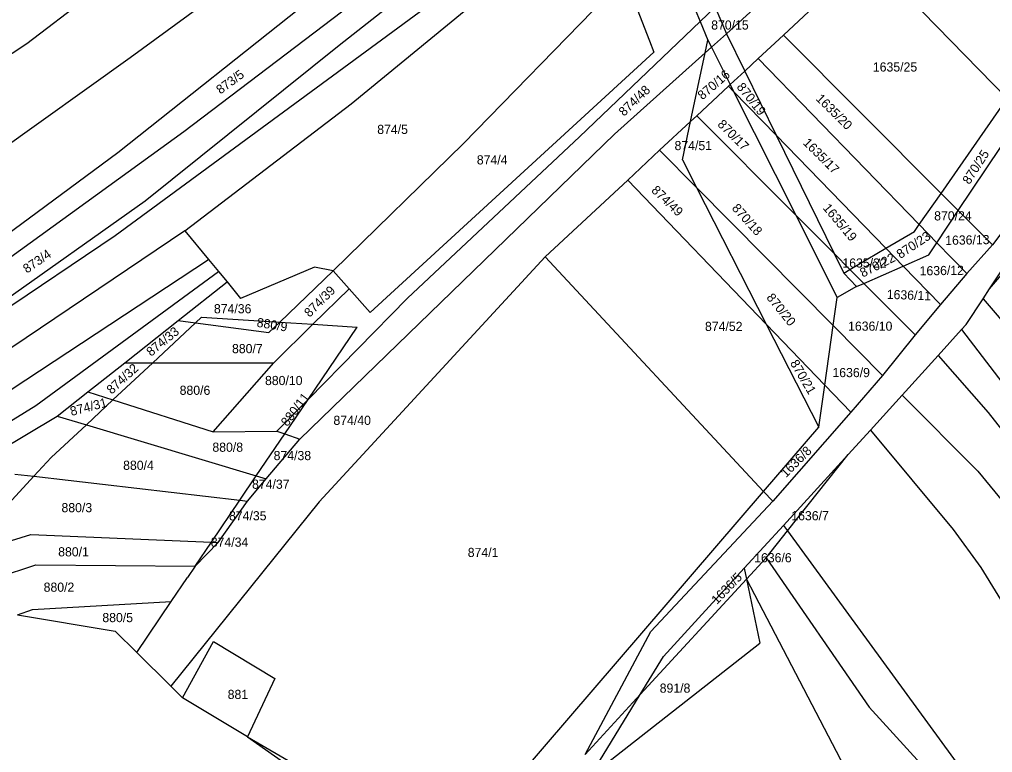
# Model space of a CAD drawing. Extents: x -563148 to -561712, y -1182311 to -1179502.
# Drawn here: x -562408.6 to -562249.3, y -1179894.3 to -1179774.2 of the extents above; entities that cross this region are included whole.
import ezdxf

# ---------------------------------------------------------------- set-up
doc = ezdxf.new("R2010")
doc.units = 0
for name, color, linetype in [('Vrstva 55', 7, 'Continuous'), ('Vrstva 56', 7, 'Continuous'), ('Vrstva 57', 7, 'Continuous')]:
    doc.layers.add(name, color=color, linetype=linetype)

msp = doc.modelspace()

# ---------------------------------------------------------------- linework, layer by layer
at = {"layer": 'Vrstva 55'}
for p, q in [((-562407.37, -1179778.19), (-562321.26, -1179711.9)), ((-562292.88, -1179776.56), (-562248.55, -1179735.96)), ((-562350.32, -1179751.09), (-562390.44, -1179780.54)), ((-562332.98, -1179755.64), (-562381.7, -1179792.64)), ((-562354.31, -1179788.07), (-562314.2, -1179755.13)), ((-562356.25, -1179778.44), (-562332.91, -1179760.03)), ((-562283.55, -1179776.79), (-562269.66, -1179763.85)), ((-562269.66, -1179763.85), (-562246.9, -1179787.18)), ((-562300.75, -1179765.98), (-562297.18, -1179774.57)), ((-562335.89, -1179794.56), (-562309.48, -1179767.37)), ((-562392.89, -1179809.58), (-562341.3, -1179771.67)), ((-562361.02, -1179771.07), (-562392.48, -1179796.07)), ((-562307.48, -1179772.55), (-562305.48, -1179777.73)), ((-562297.18, -1179774.57), (-562294.72, -1179772.22)), ((-562294.72, -1179772.22), (-562292.88, -1179776.56)), ((-562316.94, -1179793.43), (-562297.18, -1179774.57)), ((-562297.18, -1179774.57), (-562295.91, -1179777.64)), ((-562305.48, -1179777.73), (-562304.76, -1179779.6)), ((-562296.34, -1179779.67), (-562295.91, -1179777.64)), ((-562295.34, -1179778.77), (-562292.88, -1179776.56)), ((-562292.88, -1179776.56), (-562289.88, -1179782.69)), ((-562287.68, -1179780.64), (-562283.55, -1179776.79)), ((-562283.55, -1179776.79), (-562257.74, -1179802.71)), ((-562459.54, -1179811.99), (-562407.37, -1179778.19)), ((-562388.02, -1179803.91), (-562356.25, -1179778.44)), ((-562304.76, -1179779.6), (-562351.16, -1179822.19)), ((-562311.21, -1179793.04), (-562296.34, -1179779.67)), ((-562298.73, -1179790.93), (-562296.34, -1179779.67)), ((-562296.34, -1179779.67), (-562295.34, -1179778.77)), ((-562390.44, -1179780.54), (-562423.79, -1179804.26)), ((-562289.88, -1179782.69), (-562287.68, -1179780.64)), ((-562287.68, -1179780.64), (-562261.3, -1179807.82)), ((-562292.26, -1179784.9), (-562289.88, -1179782.69)), ((-562289.88, -1179782.69), (-562284.74, -1179793.17)), ((-562297.72, -1179789.99), (-562292.53, -1179785.16)), ((-562292.53, -1179785.16), (-562292.26, -1179784.9)), ((-562292.53, -1179785.16), (-562291.7, -1179786.02)), ((-562291.7, -1179786.02), (-562284.74, -1179793.17)), ((-562257.74, -1179802.71), (-562246.9, -1179787.18)), ((-562381.5, -1179808.86), (-562354.31, -1179788.07)), ((-562249.79, -1179818.34), (-562230.69, -1179789.21)), ((-562298.73, -1179790.93), (-562297.72, -1179789.99)), ((-562297.72, -1179789.99), (-562281.5, -1179806.28)), ((-562254.92, -1179805.54), (-562244.38, -1179789.76)), ((-562303.8, -1179795.65), (-562298.73, -1179790.93)), ((-562300.07, -1179797.22), (-562298.73, -1179790.93)), ((-562381.7, -1179792.64), (-562424.16, -1179823.4)), ((-562362.67, -1179842.95), (-562311.21, -1179793.04)), ((-562345.08, -1179819.89), (-562316.94, -1179793.43)), ((-562284.74, -1179793.17), (-562275.26, -1179812.55)), ((-562284.74, -1179793.17), (-562266.76, -1179811.7)), ((-562357.22, -1179815.38), (-562335.89, -1179794.56)), ((-562392.48, -1179796.07), (-562420.23, -1179816.57)), ((-562309.03, -1179800.53), (-562303.8, -1179795.65)), ((-562303.8, -1179795.65), (-562297.76, -1179801.76)), ((-562238.13, -1179796.16), (-562249.33, -1179811.15)), ((-562300.07, -1179797.22), (-562297.76, -1179801.76)), ((-562322.54, -1179813.11), (-562309.03, -1179800.53)), ((-562309.03, -1179800.53), (-562286.36, -1179824.12)), ((-562297.76, -1179801.76), (-562275.39, -1179824.36)), ((-562297.76, -1179801.76), (-562286.36, -1179824.12)), ((-562261.3, -1179807.82), (-562257.74, -1179802.71)), ((-562257.74, -1179802.71), (-562254.92, -1179805.54)), ((-562417.57, -1179824.87), (-562388.02, -1179803.91)), ((-562281.5, -1179806.28), (-562275.26, -1179812.55)), ((-562258.42, -1179810.79), (-562254.92, -1179805.54)), ((-562254.92, -1179805.54), (-562249.33, -1179811.15)), ((-562262.08, -1179808.94), (-562261.3, -1179807.82)), ((-562261.3, -1179807.82), (-562258.42, -1179810.79)), ((-562449.89, -1179848.03), (-562392.89, -1179809.58)), ((-562381.5, -1179808.86), (-562437.18, -1179846.33)), ((-562381.5, -1179808.86), (-562377.63, -1179813.55)), ((-562266.76, -1179811.7), (-562262.08, -1179808.94)), ((-562259.74, -1179812.77), (-562258.42, -1179810.79)), ((-562258.42, -1179810.79), (-562253.51, -1179815.84)), ((-562249.33, -1179811.15), (-562253.51, -1179815.84)), ((-562359.54, -1179853.24), (-562322.54, -1179813.11)), ((-562322.54, -1179813.11), (-562286.79, -1179851.51)), ((-562275.26, -1179812.55), (-562273.68, -1179815.76)), ((-562275.26, -1179812.55), (-562272.65, -1179815.16)), ((-562272.65, -1179815.16), (-562266.76, -1179811.7)), ((-562266.76, -1179811.7), (-562263.94, -1179814.61)), ((-562263.94, -1179814.61), (-562259.74, -1179812.77)), ((-562429.1, -1179847.38), (-562377.63, -1179813.55)), ((-562377.63, -1179813.55), (-562376.01, -1179815.51)), ((-562270.38, -1179817.44), (-562263.94, -1179814.61)), ((-562263.94, -1179814.61), (-562257.81, -1179820.92)), ((-562249.79, -1179818.34), (-562246.22, -1179814.15)), ((-562405.92, -1179837.47), (-562376.01, -1179815.51)), ((-562376.01, -1179815.51), (-562374.6, -1179817.22)), ((-562360.3, -1179814.77), (-562372.38, -1179819.91)), ((-562365.98, -1179823.79), (-562357.22, -1179815.38)), ((-562357.22, -1179815.38), (-562360.3, -1179814.77)), ((-562357.22, -1179815.38), (-562354.6, -1179818.32)), ((-562273.68, -1179815.76), (-562272.65, -1179815.16)), ((-562272.65, -1179815.16), (-562270.38, -1179817.44)), ((-562253.51, -1179815.84), (-562257.81, -1179820.92)), ((-562382.61, -1179823.54), (-562374.6, -1179817.22)), ((-562374.6, -1179817.22), (-562372.38, -1179819.91)), ((-562271.59, -1179817.97), (-562270.38, -1179817.44)), ((-562270.38, -1179817.44), (-562261.98, -1179825.87)), ((-562360.54, -1179824.14), (-562354.6, -1179818.32)), ((-562354.6, -1179818.32), (-562351.16, -1179822.19)), ((-562271.59, -1179817.97), (-562274.73, -1179819.74)), ((-562250.85, -1179819.96), (-562249.79, -1179818.34)), ((-562361.34, -1179836.46), (-562345.08, -1179819.89)), ((-562275.39, -1179824.36), (-562274.73, -1179819.74)), ((-562257.81, -1179820.92), (-562261.98, -1179825.87)), ((-562253.63, -1179824.19), (-562250.85, -1179819.96)), ((-562250.85, -1179819.96), (-562237.01, -1179836.23)), ((-562391.34, -1179830.44), (-562382.61, -1179823.54)), ((-562386.75, -1179830.44), (-562379.77, -1179823.92)), ((-562382.61, -1179823.54), (-562379.77, -1179823.92)), ((-562379.77, -1179823.92), (-562378.77, -1179822.98)), ((-562379.77, -1179823.92), (-562367.75, -1179825.49)), ((-562378.77, -1179822.98), (-562365.98, -1179823.79)), ((-562367.75, -1179825.49), (-562365.98, -1179823.79)), ((-562366.97, -1179830.44), (-562360.54, -1179824.14)), ((-562365.98, -1179823.79), (-562360.54, -1179824.14)), ((-562360.54, -1179824.14), (-562353.32, -1179824.6)), ((-562286.36, -1179824.12), (-562276.78, -1179834.09)), ((-562286.36, -1179824.12), (-562277.76, -1179840.99)), ((-562254.38, -1179825.02), (-562253.63, -1179824.19)), ((-562361.34, -1179836.46), (-562353.32, -1179824.6)), ((-562276.78, -1179834.09), (-562275.39, -1179824.36)), ((-562275.39, -1179824.36), (-562267.32, -1179832.52)), ((-562258.24, -1179829.27), (-562254.38, -1179825.02)), ((-562254.38, -1179825.02), (-562216.43, -1179874.8)), ((-562261.98, -1179825.87), (-562267.32, -1179832.52)), ((-562397.39, -1179835.22), (-562391.34, -1179830.44)), ((-562393.27, -1179836.53), (-562386.75, -1179830.44)), ((-562391.34, -1179830.44), (-562386.75, -1179830.44)), ((-562386.75, -1179830.44), (-562366.97, -1179830.44)), ((-562376.87, -1179841.78), (-562366.97, -1179830.44)), ((-562264.09, -1179835.73), (-562258.24, -1179829.27)), ((-562258.24, -1179829.27), (-562250.04, -1179838.57)), ((-562267.32, -1179832.52), (-562272.53, -1179838.51)), ((-562402.39, -1179839.17), (-562397.39, -1179835.22)), ((-562397.39, -1179835.22), (-562393.27, -1179836.53)), ((-562277.76, -1179840.99), (-562276.78, -1179834.09)), ((-562276.78, -1179834.09), (-562272.53, -1179838.51)), ((-562397.63, -1179840.6), (-562393.27, -1179836.53)), ((-562393.27, -1179836.53), (-562376.87, -1179841.78)), ((-562366.44, -1179841.65), (-562361.34, -1179836.46)), ((-562365.16, -1179842.09), (-562361.34, -1179836.46)), ((-562269.3, -1179841.47), (-562264.09, -1179835.73)), ((-562264.09, -1179835.73), (-562251.73, -1179848.21)), ((-562461.26, -1179871.61), (-562405.92, -1179837.47)), ((-562272.53, -1179838.51), (-562285.3, -1179853.11)), ((-562250.04, -1179838.57), (-562232.45, -1179861.25)), ((-562456.35, -1179871.27), (-562402.39, -1179839.17)), ((-562402.39, -1179839.17), (-562397.63, -1179840.6)), ((-562403.37, -1179845.97), (-562397.63, -1179840.6)), ((-562397.63, -1179840.6), (-562369.81, -1179848.98)), ((-562376.87, -1179841.78), (-562366.44, -1179841.65)), ((-562366.44, -1179841.65), (-562365.16, -1179842.09)), ((-562286.79, -1179851.51), (-562277.76, -1179840.99)), ((-562272.93, -1179845.47), (-562269.3, -1179841.47)), ((-562269.3, -1179841.47), (-562255.77, -1179857.73)), ((-562369.81, -1179848.98), (-562365.16, -1179842.09)), ((-562368.18, -1179849.47), (-562362.67, -1179842.95)), ((-562365.16, -1179842.09), (-562362.67, -1179842.95)), ((-562406.22, -1179849.04), (-562403.37, -1179845.97)), ((-562283.53, -1179857.07), (-562272.93, -1179845.47)), ((-562282.86, -1179857.99), (-562272.93, -1179845.47)), ((-562418.44, -1179862.21), (-562406.22, -1179849.04)), ((-562409.31, -1179848.68), (-562406.22, -1179849.04)), ((-562406.22, -1179849.04), (-562372.52, -1179852.97)), ((-562372.52, -1179852.97), (-562369.81, -1179848.98)), ((-562371.26, -1179853.12), (-562368.18, -1179849.47)), ((-562369.81, -1179848.98), (-562368.18, -1179849.47)), ((-562251.73, -1179848.21), (-562238.06, -1179864.89)), ((-562337.9, -1179911.04), (-562286.79, -1179851.51)), ((-562286.79, -1179851.51), (-562285.3, -1179853.11)), ((-562359.54, -1179853.24), (-562383.82, -1179883.4)), ((-562377.16, -1179859.84), (-562372.52, -1179852.97)), ((-562376.08, -1179859.89), (-562371.26, -1179853.12)), ((-562372.52, -1179852.97), (-562371.26, -1179853.12)), ((-562285.3, -1179853.11), (-562305.25, -1179874.46)), ((-562289.96, -1179864.1), (-562283.53, -1179857.07)), ((-562283.53, -1179857.07), (-562282.86, -1179857.99)), ((-562418.44, -1179862.21), (-562406.7, -1179858.58)), ((-562406.7, -1179858.58), (-562377.16, -1179859.84)), ((-562286.36, -1179862.39), (-562282.86, -1179857.99)), ((-562282.86, -1179857.99), (-562253.82, -1179897.86)), ((-562255.77, -1179857.73), (-562251.21, -1179863.98)), ((-562379.82, -1179863.77), (-562377.16, -1179859.84)), ((-562376.08, -1179859.89), (-562379.82, -1179863.77)), ((-562377.16, -1179859.84), (-562376.08, -1179859.89)), ((-562289.59, -1179865.9), (-562286.36, -1179862.39)), ((-562286.36, -1179862.39), (-562269.49, -1179886.86)), ((-562415.13, -1179866.6), (-562405.92, -1179863.53)), ((-562405.92, -1179863.53), (-562379.82, -1179863.77)), ((-562379.82, -1179863.77), (-562381.05, -1179865.59)), ((-562251.21, -1179863.98), (-562228.29, -1179901.51)), ((-562383.73, -1179869.55), (-562381.05, -1179865.59)), ((-562289.96, -1179864.1), (-562303.15, -1179878.53)), ((-562289.96, -1179864.1), (-562289.59, -1179865.9)), ((-562306.99, -1179884.79), (-562289.59, -1179865.9)), ((-562289.59, -1179865.9), (-562287.43, -1179876.36)), ((-562289.59, -1179865.9), (-562267.5, -1179908.16)), ((-562406.44, -1179870.83), (-562383.73, -1179869.55)), ((-562389.38, -1179877.9), (-562383.73, -1179869.55)), ((-562408.89, -1179871.73), (-562406.44, -1179870.83)), ((-562408.89, -1179871.73), (-562392.9, -1179874.42)), ((-562389.38, -1179877.9), (-562392.9, -1179874.42)), ((-562316, -1179894.57), (-562305.25, -1179874.46)), ((-562381.89, -1179885.31), (-562376.82, -1179876.08)), ((-562376.82, -1179876.08), (-562366.78, -1179882.16)), ((-562315.14, -1179898.08), (-562287.43, -1179876.36)), ((-562389.38, -1179877.9), (-562383.82, -1179883.4)), ((-562306.99, -1179884.79), (-562303.15, -1179878.53)), ((-562366.78, -1179882.16), (-562371.24, -1179891.71)), ((-562383.82, -1179883.4), (-562381.89, -1179885.31)), ((-562371.24, -1179891.71), (-562381.89, -1179885.31)), ((-562316, -1179894.57), (-562306.99, -1179884.79)), ((-562315.14, -1179898.08), (-562306.99, -1179884.79)), ((-562269.49, -1179886.86), (-562250.41, -1179907.72)), ((-562371.24, -1179891.71), (-562340.08, -1179913.59)), ((-562371.24, -1179891.71), (-562337.9, -1179911.04))]:
    msp.add_line(p, q, dxfattribs=at)
at = {"layer": 'Vrstva 56'}
for p, q in [((-562295.91, -1179777.64), (-562295.34, -1179778.77)), ((-562295.34, -1179778.77), (-562292.26, -1179784.9)), ((-562292.26, -1179784.9), (-562291.7, -1179786.02)), ((-562291.7, -1179786.02), (-562281.5, -1179806.28)), ((-562281.5, -1179806.28), (-562274.73, -1179819.74)), ((-562271.59, -1179817.97), (-562273.68, -1179815.76))]:
    msp.add_line(p, q, dxfattribs=at)

# ---------------------------------------------------------------- texts
at = {"layer": 'Vrstva 57'}
for s, p in [('870/15', (-562295.36, -1179775.89)), ('1635/25', (-562268.9, -1179782.76)), ('874/5', (-562350.02, -1179792.98)), ('874/51', (-562301.36, -1179795.63)), ('874/4', (-562333.72, -1179797.97)), ('870/24', (-562258.87, -1179807.14)), ('1635/22', (-562273.89, -1179814.86)), ('874/36', (-562376.75, -1179822.35)), ('874/52', (-562296.38, -1179825.24)), ('1636/10', (-562272.96, -1179825.2)), ('880/7', (-562373.79, -1179828.88)), ('1636/9', (-562275.52, -1179832.8)), ('880/10', (-562368.39, -1179834.1)), ('880/6', (-562382.36, -1179835.7)), ('874/40', (-562357.19, -1179840.62)), ('880/8', (-562377, -1179845.02)), ('874/38', (-562366.98, -1179846.39)), ('880/4', (-562391.61, -1179847.98)), ('874/37', (-562370.51, -1179851.08)), ('880/3', (-562401.7, -1179854.92)), ('874/35', (-562374.28, -1179856.25)), ('1636/7', (-562282.25, -1179856.24)), ('874/34', (-562377.26, -1179860.57)), ('880/1', (-562402.24, -1179862.15)), ('874/1', (-562335.21, -1179862.25)), ('1636/6', (-562288.33, -1179863.12)), ('880/2', (-562404.62, -1179867.94)), ('880/5', (-562395.01, -1179872.92)), ('891/8', (-562303.79, -1179884.47)), ('881', (-562374.5, -1179885.5))]:
    msp.add_text(s, height=1.5, dxfattribs=at).set_placement(p)
for s, rotation, p in [('873/5', 36.524, (-562375.68, -1179786.54)), ('870/16', 40.6012, (-562296.8, -1179787.48)), ('874/48', 43.6296, (-562309.64, -1179790.18)), ('870/19', 308.6172, (-562291.28, -1179785.32)), ('1635/20', 315.2535, (-562278.33, -1179787.32)), ('870/17', 314.9509, (-562294.44, -1179791.52)), ('1635/17', 315.2758, (-562280.45, -1179794.56)), ('870/25', 57.1937, (-562253.1, -1179801.36)), ('874/49', 316.1771, (-562305.27, -1179802.35)), ('870/18', 312.0106, (-562292.07, -1179805.21)), ('1635/19', 309.8748, (-562277.17, -1179805.15)), ('870/23', 33.5305, (-562264.4, -1179813.47)), ('1636/13', 1.0261, (-562257.05, -1179811.15)), ('873/4', 34.4667, (-562407.36, -1179815.86)), ('870/22', 26.8739, (-562270.55, -1179816.51)), ('1636/12', 0.7639, (-562261.24, -1179816.14)), ('874/39', 45, (-562361.09, -1179823.09)), ('870/20', 308.8845, (-562286.41, -1179819.81)), ('1636/11', 357.8483, (-562266.65, -1179819.97)), ('880/9', 350.7673, (-562369.82, -1179824.54)), ('874/33', 39.3737, (-562387.04, -1179829.48)), ('870/21', 300.5216, (-562282.51, -1179830.49)), ('874/32', 42.4589, (-562393.49, -1179835.69)), ('874/31', 14.6419, (-562400.06, -1179839.16)), ('880/11', 52.6506, (-562364.73, -1179840.98)), ('1636/8', 45, (-562283.12, -1179849.35)), ('1636/5', 46.2276, (-562294.41, -1179870.11))]:
    msp.add_text(s, height=1.5, rotation=rotation, dxfattribs=at).set_placement(p)

doc.saveas('drawing.dxf')
